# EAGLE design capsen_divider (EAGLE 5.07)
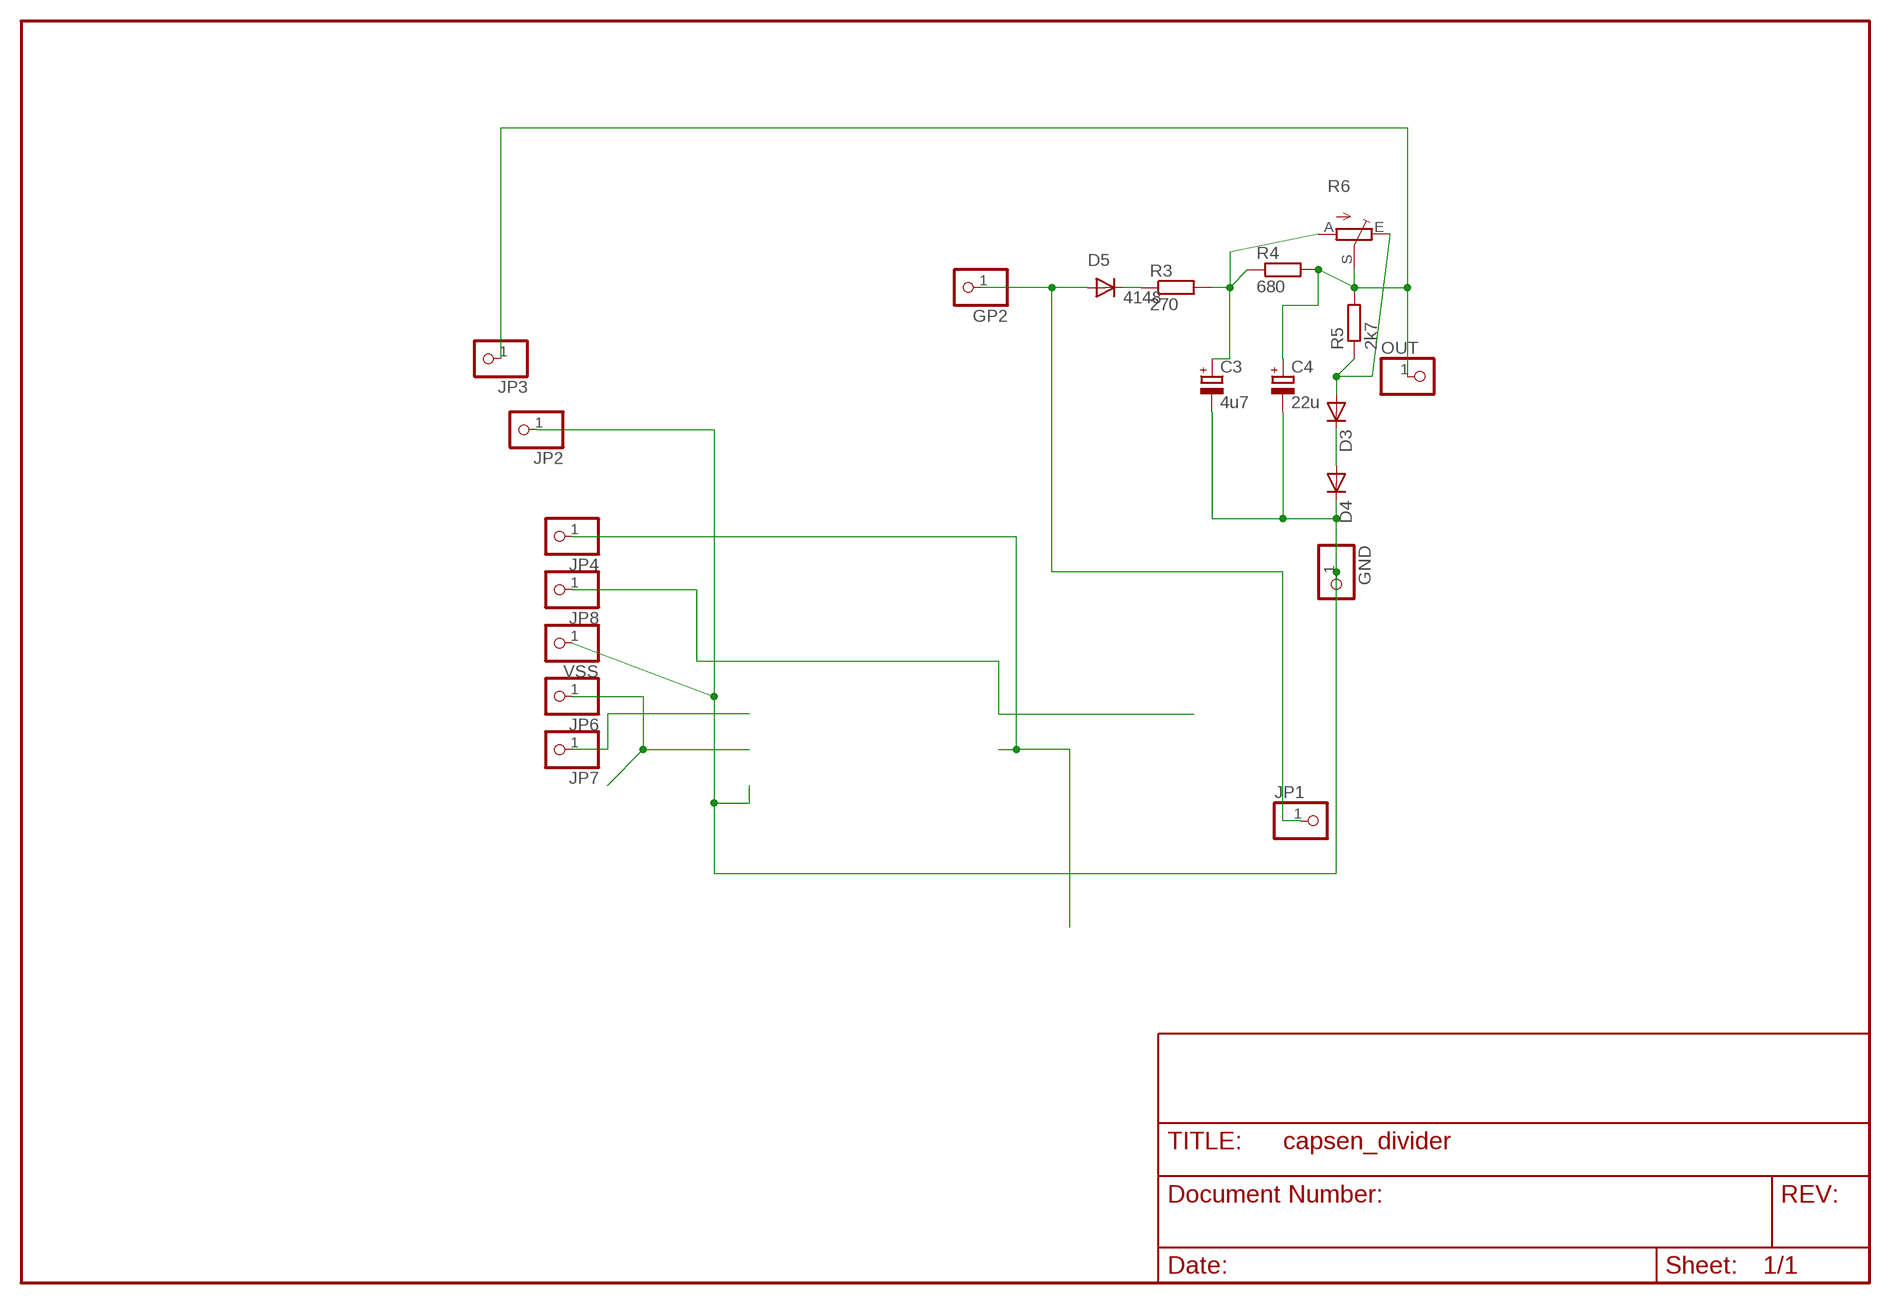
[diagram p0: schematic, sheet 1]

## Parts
C3  4u7  CPOL-EUSMCA  [SMC_A]
C4  22u  CPOL-EUSMCA  [SMC_A]
D3  DIODE-SOD80C  [SOD80C]
D4  DIODE-SOD80C  [SOD80C]
D5  4148  DIODE-SOD80C  [SOD80C]
GND  PINHD-1X11X0.4  [1X01]
GP2  PINHD-1X11X0.4  [1X01]
JP1  PINHD-1X1  [1X01]
JP2  PINHD-1X1  [1X01]
JP3  PINHD-1X1  [1X01]
JP4  PINHD-1X1  [1X01]
JP6  PINHD-1X1  [1X01]
JP7  PINHD-1X1  [1X01]
JP8  PINHD-1X1  [1X01]
OUT  PINHD-1X11X0.4  [1X01]
R3  270  R-EU_R0805  [R0805]
R4  680  R-EU_R0805  [R0805]
R5  2k7  R-EU_R0805  [R0805]
R6  TRIM_EU-CA6V  [CA6V]
VSS  PINHD-1X1  [1X01]

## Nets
DR1: D5.C R3.1
DR2: D3.A R5.1 R6.E
GND: C3.- C4.- D4.C GND.1 JP2.1 VSS.1
GP0: JP8.1
GP1: JP4.1
GP2: D5.A GP2.1 JP1.1
GP3: JP7.1
N$2: D3.C D4.A
N$5: JP6.1
OUT: C4.+ JP3.1 OUT.1 R4.2 R5.2 R6.S
RRC: C3.+ R3.2 R4.1 R6.A

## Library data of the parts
C3 C4 = rcl:CPOL-EU: POLARIZED CAPACITOR, European symbol
D3-D5 = diode:DIODE-: DIODE
GND GP2 OUT = pinhead:PINHD-1X1: PIN HEADER
JP1-JP4 JP6-JP8 VSS = pinhead(2):PINHD-1X1: PIN HEADER
R3-R5 = rcl:R-EU_: RESISTOR, European symbol
R6 = pot:TRIM_EU-: POTENTIOMETER

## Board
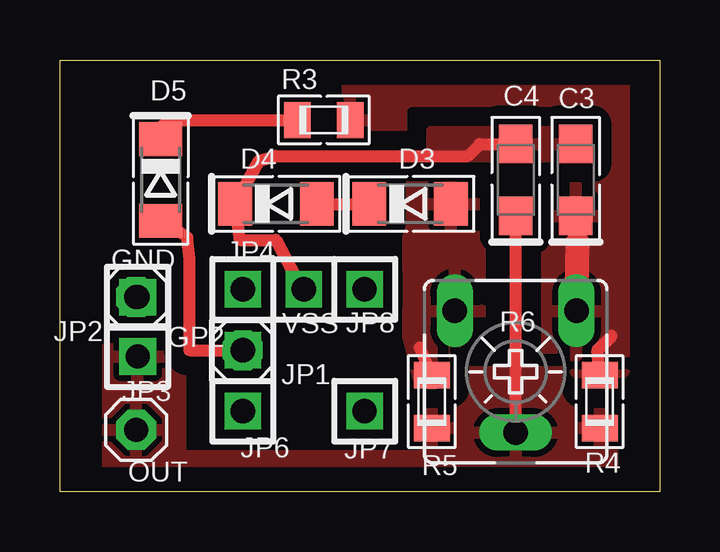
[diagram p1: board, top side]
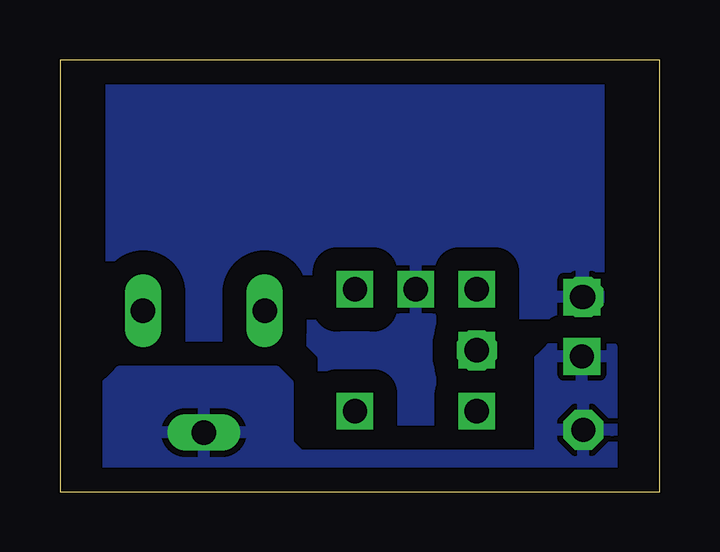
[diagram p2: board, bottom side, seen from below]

Size 25 x 18 mm. Coordinates in mm from the lower left corner, seen from the top.
Outline: 0,0 0,18 25,18 25,0 0,0
Copper layers (1*16): Top 0.035mm / dielectric 1.5mm / Bottom 0.035mm
Design rules "default": minimum track width 10mil, minimum drill 24mil, track to track 8mil, track to pad 8mil, pad to pad 8mil, via to via 8mil, smd to smd 8mil, copper to edge 40mil, drill to drill 8mil, minimum pad ring 10mil, minimum via ring 8mil, stop-mask expansion 4mil, vias tented up to drill 0mil, thermal gap 10mil

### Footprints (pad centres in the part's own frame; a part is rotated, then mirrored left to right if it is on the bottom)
SMC_A = smd 1.6 x 1.4: + -1.5,0; - 1.5,0
SOD80C = smd 1.4 x 1.8: A 1.7,0; C -1.7,0
1X01 = drill 1 pad 1.676 octagon: 1 0,0
1X01' = drill 1.016 square: 1 0,0
R0805 = smd 1.1 x 1.5: 1 -1.1,0; 2 1.1,0
CA6V = drill 1.016 long: A -2.54,-2.54; E 2.54,-2.54; S 0,2.54

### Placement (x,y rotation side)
C3  21.5,13 90 top
C4  19,13 90 top
D3  14.6,12 0 top
D4  9,12 0 top
D5  4.2,13 270 top
GND  3.17,8.11 0 top
GP2  7.62,5.89 0 top
JP1  [1X01']  7.62,5.89 90 top
JP2  [1X01']  3.24,8.11 90 top
JP3  [1X01']  3.24,5.64 90 top
JP4  [1X01']  7.62,8.43 0 top
JP6  [1X01']  7.62,3.35 0 top
JP7  [1X01']  12.7,3.35 0 top
JP8  [1X01']  12.7,8.43 0 top
OUT  3.17,2.57 0 top
R3  11,15.5 0 top
R4  22.5,3.75 270 top
R5  15.5,3.75 270 top
R6  19,5 180 top
VSS  [1X01']  10.16,8.43 0 top

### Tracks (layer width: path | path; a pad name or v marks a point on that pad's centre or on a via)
DR1
  Top 0.5: D5.C 4.2,15.2 4.5,15.5 R3.1
DR2
  Top 0.5: R5.1 15,6
  pour Top (isolate 0.8, rank 3): 17.5,4.5 17.5,13 14.5,13 14.5,6.5 15,4.5
GND
  Top 0.5: VSS.1 10,8.59 9,10.5 7.5,10.5 D4.C 8.3,13.8 9,14 17,14 17.5,14.5 C4.-
  pour Bottom (isolate 1, rank 3): 2.54,17.32 22.86,17.32 22.86,-0.46 2.54,-0.46
  pour Top (isolate 0.5): 15.5,14 21.5,14 21.5,15 15.5,15
GP2
  Top 0.5: GP2.1 5.4,5.89 5.4,9.7 5.31,10.61 D5.A
N$2
  Top 0.5: D4.A D3.C
OUT
  Top 0.5: 19.05,2.45 R6.S C4.+
  pour Top (isolate 0.813, rank 2): 16,5 22.5,5 23,4.5 23,0 22.5,-0.5 2.5,-0.5 2,0 2,6 4.5,6 5,5.5 5,1.5 15,1.5 15.5,2 15.5,4.5
  pour Bottom (isolate 0.5, rank 2): 16,5 22.5,5 23,4.5 23,0 22.5,-0.5 2.5,-0.5 2,0 2,6 4.5,6 5,5.5 5,1.5 15,1.5 15.5,2 15.5,4.5
RRC
  Top 0.5: R4.1 22.41,5.92 23,6.5
  Top 1: R6.A 21.59,10.38
  pour Top (isolate 0.8, rank 2): 12,17.5 22.5,17.5 23.5,17 23.5,5 21.5,5 21.5,6 20,6 20,15 12,15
